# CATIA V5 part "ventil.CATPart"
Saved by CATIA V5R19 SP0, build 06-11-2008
Part number: kompresny v
Bounding box of the stored display mesh (mm): x -19 to 19, y -9 to 9, z 0 to 87
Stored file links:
  C:\Users\Jozef Drozd\Desktop\zostava\party\ventil.CATPart
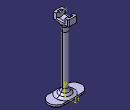
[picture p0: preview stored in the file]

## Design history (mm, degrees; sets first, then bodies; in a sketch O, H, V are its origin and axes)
Body1 (main body)
  Sketch1 on xy-plane, origin (0, 0, 0), H (1, 0, 0), V (0, 1, 0)
    construction line L1 (-10, 0) -> (10, 0)
    point P1 (-10, 0)
    line L2 (-10, 9) -> (10, 9)
    line L3 (10, -9) -> (-10, -9)
    arc A1 centre (10, 0) radius 9 from (10, 9) to (10, -9) cw
    arc A2 centre (-10, 0) radius 9 from (-10, -9) to (-10, 9) cw
    distance L1 L2 = 9
    coincidence: P1 H
    horizontal: L1 H
    tangency: A1 L2, A2 L2, A1 L3, A2 L3
  Pad1: profile Sketch1, direction (0, 0, 1), length 3
  Chamfer1: length 1, angle 45, on start face of Pad1
  Sketch2 on end face of Pad1, origin (0, 0, 3), H (1, 0, 0), V (0, 1, 0)
    circle A1 centre (0, 0) radius 3
    point P1 (0, -3)
    coincidence: A1 P1, P1 V
  Pad2: profile Sketch2, direction (0, 0, 1), length 75.14
  Chamfer2: length 5, angle 45, on edge [end face of Pad1 | face of Pad2 from Sketch2.A1]
  Fillet1: radius 5, on edge [face of Pad2 from Sketch2.A1 | face of Chamfer2]; edge [face of Chamfer2 | end face of Pad1]
  Sketch3 on end face of Pad2, origin (0, 0, 78.14), H (1, 0, 0), V (0, 1, 0)
    construction line L1 (0, 0) -> (0, 0)
    line L2 (-5, 0) -> (-5, 0)
    line L3 (5, 0) -> (5, 0)
    line L4 (-4, 9) -> (4, 9)
    line L5 (4, -9) -> (-4, -9)
    line L6 (5, 8) -> (5, -8)
    line L7 (-5, 8) -> (-5, -8)
    arc A1 centre (4, 8) radius 1 from (4, 9) to (5, 8) cw
    arc A2 centre (-4, 8) radius 1 from (-5, 8) to (-4, 9) cw
    arc A3 centre (-4, -8) radius 1 from (-5, -8) to (-4, -9) ccw
    arc A4 centre (4, -8) radius 1 from (5, -8) to (4, -9) cw
    distance L6 V = 5
    distance V L7 = 5
    radius A1 = 1
    radius A2 = 1
    radius A3 = 1
    radius A4 = 1
    distance L5 H = 9
    distance L4 H = 9
    horizontal: L1 H, L4 H, L5 H
    vertical: L6 V, L7 V
    tangency: A1 L4, A1 L6, A2 L7, A2 L4, A3 L7, A3 L5, A4 L6, A4 L5
  Pad3: profile Sketch3, direction (0, 0, 1), length 2, opposite side length 2
  Chamfer3: length 10, second length 1, on edge [face of Pad2 from Sketch2.A1 | start face of Pad3]
  Fillet2: radius 5, on edge [start face of Pad3 | face of Chamfer3]
  Sketch4 on yz-plane, origin (0, 0, 0), H (0, 1, 0), V (0, 0, 1)
    point P1 (0, 87)
    coincidence: P1 V
  Sketch5 on end face of Pad3, origin (0, 0, 80.14), H (1, 0, 0), V (0, 1, 0)
    line L1 (-4, 9) -> (4, 9)
    line L2 (5, 8) -> (5, 5)
    line L3 (5, 5) -> (-5, 5)
    line L4 (-5, 5) -> (-5, 8)
    point P1 (5, 5)
    point P2 (-5, 5)
    arc A1 centre (4, 8) radius 1 from (4, 9) to (5, 8) cw
    point P3 (4, 9)
    point P4 (5, 8)
    arc A2 centre (-4, 8) radius 1 from (-5, 8) to (-4, 9) cw
    point P6 (-5, 8)
    point P7 (-4, 9)
    reference projected line E1 (5, -8) -> (5, 8) from edge [face of Pad3 from Sketch3.L6 | end face of Pad3]
    reference projected line E2 (-5, 8) -> (-5, -8) from edge [face of Pad3 from Sketch3.L7 | end face of Pad3]
    reference projected line E3 (4, 9) -> (-4, 9) from edge [face of Pad3 from Sketch3.L4 | end face of Pad3]
    point P9 (4, -9)
    point P10 (-4, -9)
    line L5 (-4, -9) -> (4, -9)
    point P11 (5, -8)
    arc A3 centre (4, -8) radius 1 from (4, -9) to (5, -8) ccw
    point P13 (5, -5)
    line L6 (5, -8) -> (5, -5)
    point P14 (-5, -5)
    line L7 (5, -5) -> (-5, -5)
    point P15 (-5, -8)
    line L8 (-5, -5) -> (-5, -8)
    arc A4 centre (-4, -8) radius 1 from (-5, -8) to (-4, -9) ccw
    radius A1 = 1
    radius A2 = 1
    distance L2 E1 = 0
    distance L4 E2 = 0
    distance L1 E3 = 0
    horizontal: L1 H, L3 H
    vertical: L2 V, L4 V
    tangency: A1 L1, A1 L2, A2 L4, A2 L1
    symmetry: P3 P9 H, P7 P10 H, L1 L5 H, P4 P11 H, A1 A3 H, P1 P13 H, L2 L6 H, P2 P14 H, L3 L7 H, P6 P15 H, L4 L8 H, A2 A4 H
  Pad4: profile Sketch5, direction (0, 0, 1), length 3
  Sketch6 on end face of Pad4, origin (0, 0, 83.14), H (1, 0, 0), V (0, 1, 0)
    line L1 (0, 7) -> (2, 7)
    line L2 (2, 7) -> (2, 5)
    line L3 (6, 5) -> (6, -5)
    line L4 (6, -5) -> (2, -5)
    line L5 (2, -5) -> (2, -7)
    line L6 (2, -7) -> (0, -7)
    point P6 (2, -7)
    line L7 (2, 5) -> (6, 5)
    axis line L8 (0, -10) -> (0, -15)
    point P7 (0, -10)
    line L9 (0, 7) -> (0, -7)
    distance L3 L9 = 6
    horizontal: L1 H, L4 H, L6 H, L7 H
    vertical: L2 V, L3 V, L5 V, L8 V, L9 V
    coincidence: P6 L2, P7 V
  Groove1: profile Sketch6, axis Sketch6.L8, angle 360
  Fillet3: radius 1, on edge [face of Pad4 | face of Groove1 from Sketch6.L3]; edge [face of Groove1 from Sketch6.L3 | face of Pad4]
  DatumSurface1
